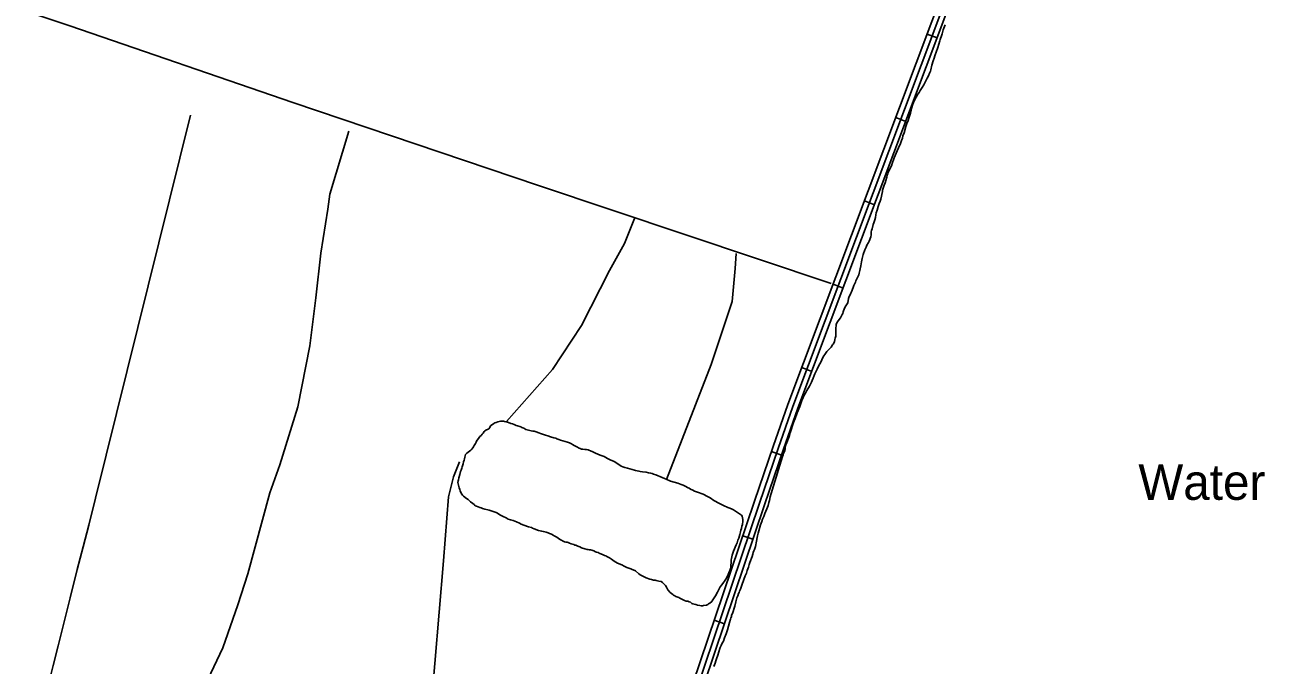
# Model space of a CAD drawing. Extents: x 3177185 to 3215018, y 812988 to 838321.
# Drawn here: x 3191874 to 3195360, y 828371 to 830168 of the extents above; entities that cross this region are included whole.
import ezdxf

# ---------------------------------------------------------------- set-up
doc = ezdxf.new("R2010")
doc.units = 0
for name, color, linetype in [('V-RIVR-IDEN', 7, 'Continuous'), ('V-ROAD-CNTR', 7, 'Continuous'), ('V-TOPO-SHOR', 7, 'Continuous')]:
    doc.layers.add(name, color=color, linetype=linetype)

msp = doc.modelspace()

# ---------------------------------------------------------------- linework, layer by layer
at = {"layer": 'V-ROAD-CNTR'}
for p, q in [((3194436, 830131.4), (3194407.9, 830141.9)), ((3194347.9, 829897.4), (3194319.9, 829908)), ((3194259.9, 829663.4), (3194231.8, 829674)), ((3194171.8, 829429.4), (3194143.7, 829440)), ((3194083.8, 829195.5), (3194055.7, 829206)), ((3193998.9, 828960.8), (3193970.5, 828970.5)), ((3193918.4, 828724.2), (3193890, 828733.8)), ((3193838.5, 828487.3), (3193810, 828496.9))]:
    msp.add_line(p, q, dxfattribs=at)
for points in [[(3195718.2, 830676.6), (3195274.2, 830649.9), (3194889.5, 830614.4), (3194691.9, 830585.5), (3194661.2, 830576.1), (3194620.2, 830551.7), (3194549, 830454.1), (3194520.5, 830401.6), (3194435.4, 830172.3), (3194030.8, 829097.3), (3193989.4, 828979.4), (3193936.9, 828826), (3193655, 827990.6), (3193436.5, 827403.7), (3193231, 826864.7), (3193164.5, 826701.3), (3193149.1, 826671.9), (3192991.1, 826299.7)], [(3195718.9, 830661.6), (3195275.3, 830635), (3194891.3, 830599.5), (3194695.2, 830570.8), (3194667.4, 830562.3), (3194630.5, 830540.4), (3194561.7, 830446.1), (3194534.2, 830395.4), (3194449.4, 830167), (3194044.9, 829092.1), (3194003.6, 828974.5), (3193951.1, 828821.2), (3193669.2, 827985.5), (3193450.5, 827398.5), (3193245, 826859.2), (3193178.1, 826695), (3193162.7, 826665.5), (3193032.9, 826359.8)], [(3194509.8, 830415.8), (3194421.3, 830177.5), (3194016.7, 829102.4), (3193975.3, 828984.3), (3193922.7, 828830.8), (3193640.9, 827995.6), (3193422.4, 827409), (3193217, 826870.2), (3193150.8, 826707.7), (3193135.5, 826678.3), (3192977.5, 826306.2), (3192932.7, 826221.9), (3192888.6, 826141.9), (3192857.2, 826099.8), (3192822.1, 826060.4), (3192768.4, 826005.4), (3192712.2, 825957.6), (3192677.2, 825934.2), (3192621.8, 825905.4)]]:
    msp.add_lwpolyline(points, dxfattribs=at)
at = {"layer": 'V-TOPO-SHOR'}
msp.add_line((3192072.2, 828839.8), (3192339, 829914.9), dxfattribs=at)
for points in [[(3190402.1, 830713), (3190848.1, 830553.1), (3191672.8, 830275.4), (3192001, 830166), (3192626.6, 829950), (3193316.6, 829717.1), (3194138.6, 829442.2)], [(3194245.1, 829561.1), (3194249.6, 829573.2), (3194250.5, 829579.2), (3194250.5, 829582.6), (3194251.1, 829587.1), (3194252, 829590.7), (3194253.2, 829596.1), (3194256.2, 829607.6), (3194258, 829612.2), (3194259.5, 829615.5), (3194261.3, 829620.6), (3194262.5, 829627.3), (3194264.3, 829635.4), (3194265.2, 829640.2), (3194267.6, 829648.4), (3194270.6, 829658.1), (3194270.9, 829661.1), (3194273.3, 829666.5), (3194276.3, 829673.2), (3194277.5, 829678.9), (3194282.2, 829700.6), (3194282.8, 829704), (3194285.5, 829712.4), (3194287.6, 829718.1), (3194289.7, 829724.5), (3194291.5, 829731.4), (3194294.5, 829740.5), (3194296, 829746.2), (3194297.2, 829749.9), (3194298.4, 829753.8), (3194301.1, 829760.7), (3194307.4, 829772.2), (3194310.7, 829781.9), (3194313.1, 829789.1), (3194314.9, 829795.2), (3194320.9, 829808.2), (3194324, 829814.2), (3194327.9, 829822.7), (3194333.3, 829835.6), (3194336.3, 829844.1), (3194338.4, 829850.1), (3194339.9, 829856.5), (3194343.2, 829865.2), (3194348.3, 829883.4), (3194351, 829891.5), (3194354.3, 829900), (3194357.3, 829909), (3194360.9, 829920.8), (3194361.8, 829923.8), (3194364.1, 829933.2), (3194368, 829945.3), (3194372.2, 829956.7), (3194382.2, 829973.4), (3194385.5, 829978.8), (3194388.2, 829983.9), (3194391.8, 829989.7), (3194393.9, 829992.7), (3194398.4, 830000.3), (3194402, 830007.5), (3194405, 830012.9), (3194407.7, 830018.4), (3194411.3, 830025), (3194414.9, 830032.9), (3194417.3, 830038.3), (3194418.5, 830041.6), (3194421.2, 830054.9), (3194424.5, 830067.3), (3194427.2, 830075.2), (3194429.6, 830080.9), (3194430.5, 830083.9), (3194432.9, 830091.2), (3194437.7, 830105.1), (3194444, 830123.5), (3194444.9, 830126.8), (3194447.9, 830137.4), (3194450, 830143.1), (3194452.1, 830150.4), (3194453.3, 830154.6), (3194458.1, 830168.5)], [(3192006.6, 827411.3), (3192062.7, 827740.9), (3192079.6, 827785.8), (3192099.2, 827836.3), (3192135.7, 827895.2), (3192172.1, 827951.3), (3192247.9, 828057.9), (3192304, 828147.6), (3192379.7, 828313.1), (3192430.2, 828419.7), (3192472.3, 828540.4), (3192500.3, 828627.3), (3192562, 828854.5), (3192590.1, 828933.1), (3192640.6, 829095.8), (3192674.3, 829266.9), (3192691.1, 829401.6), (3192705.1, 829527.8), (3192724.7, 829651.2), (3192730.4, 829693.3), (3192783.7, 829870)], [(3193226.9, 829055.1), (3193355.9, 829201), (3193437.3, 829324.4), (3193515.8, 829478.7), (3193557.9, 829554.4), (3193585.9, 829624.6)], [(3193972.8, 828862.5), (3194001.9, 828956.4), (3194004, 828961.3), (3194004.9, 828965.5), (3194007.9, 828972.4), (3194009.1, 828978.8), (3194009.7, 828983.9), (3194011.5, 828989), (3194014.2, 828996), (3194015.4, 829000.5), (3194018.4, 829008.1), (3194020.2, 829012.3), (3194021.4, 829015.9), (3194023.5, 829023.2), (3194026.5, 829031.9), (3194031, 829046.7), (3194032.8, 829051.6), (3194037.3, 829063.3), (3194043.3, 829079.3), (3194050.2, 829096.9), (3194051.4, 829099.9), (3194054.1, 829108.6), (3194055.9, 829114.1), (3194059.5, 829121.9), (3194061.9, 829126.8), (3194066.1, 829134.6), (3194068.2, 829138.2), (3194070.3, 829141.9), (3194073, 829146.7), (3194075.2, 829149.4), (3194077.3, 829154), (3194083, 829165.4), (3194084.8, 829169.7), (3194088.1, 829176.9), (3194090.8, 829184.2), (3194092.9, 829188.7), (3194097.1, 829198.1), (3194098.9, 829201.7), (3194100.4, 829205), (3194102.5, 829208.9), (3194105.2, 829214.1), (3194106.7, 829217.1), (3194110.9, 829224.9), (3194112.4, 829228), (3194114.5, 829232.8), (3194118.1, 829239.4), (3194120.5, 829243.1), (3194122.3, 829246.1), (3194125.9, 829251.5), (3194135.9, 829260.9), (3194138.3, 829263.9), (3194142.5, 829269.7), (3194144.3, 829272.1), (3194147.6, 829278.4), (3194148.8, 829285.4), (3194150, 829289), (3194151.2, 829294.7), (3194151.2, 829305), (3194151.2, 829309.2), (3194151.2, 829313.8), (3194151.2, 829318), (3194152.4, 829323.4), (3194152.9, 829327), (3194155.6, 829334), (3194164.4, 829345.8), (3194166.8, 829350), (3194169.5, 829355.4), (3194171, 829358.2), (3194172.5, 829362.4), (3194176.1, 829373), (3194179.7, 829379.3), (3194181.8, 829382), (3194183.6, 829384.7), (3194184.8, 829388.4), (3194187.2, 829400.1), (3194189.3, 829405.3), (3194192.3, 829411.9), (3194193.8, 829415.2), (3194195.6, 829418.6), (3194199.8, 829431), (3194202.2, 829436.4), (3194204.9, 829442.7), (3194206.4, 829446.4), (3194207.6, 829449.4), (3194209.7, 829453.9), (3194213.9, 829462.7), (3194215.7, 829466.6), (3194216.9, 829471.4), (3194219, 829478.7), (3194220.2, 829483.5), (3194221.4, 829491.7), (3194223.8, 829503.4), (3194225, 829507.7), (3194225.3, 829512.2), (3194226.2, 829515.8), (3194228.6, 829523.7), (3194233.1, 829537), (3194236.7, 829544.5), (3194238.8, 829549.9), (3194243, 829556.9), (3194245.1, 829561.1)], [(3193675.7, 828892.4), (3193801.9, 829215), (3193860.8, 829391.7), (3193869.3, 829484.3), (3193872.1, 829526.4)], [(3193126.4, 828974.7), (3193129.1, 828977.4), (3193131.8, 828980.5), (3193134.1, 828984.1), (3193136.3, 828987.6), (3193139.5, 828993.4), (3193141.3, 828996.5), (3193142.7, 828999.2), (3193144.5, 829002.3), (3193147.7, 829006.8), (3193152.2, 829013), (3193155.3, 829015.2), (3193158.5, 829019.3), (3193161.2, 829022.4), (3193163.9, 829026.4), (3193166.2, 829028.6), (3193170.2, 829031.3), (3193173.4, 829032.6), (3193177, 829034.3), (3193179.7, 829037.9), (3193182, 829042.4), (3193191.4, 829049), (3193194.1, 829050.8), (3193197.3, 829051.6), (3193202.7, 829053.8), (3193210.3, 829056), (3193214.3, 829056), (3193217.9, 829055.5), (3193221.5, 829055), (3193225.5, 829053.7), (3193229.5, 829053.2), (3193232.7, 829051.8), (3193238.5, 829049.5), (3193243.8, 829048.2), (3193248.3, 829046.3)], [(3193248.3, 829046.3), (3193254.1, 829044), (3193257.7, 829042.7)], [(3193257.7, 829042.7), (3193263.9, 829040.8), (3193266.6, 829039.5), (3193270.2, 829038.1), (3193275.1, 829036.3), (3193281.3, 829032.6), (3193292, 829029.9), (3193295.6, 829028.9), (3193300.5, 829028), (3193304.6, 829027.5), (3193310.4, 829026.1), (3193317.5, 829023.4), (3193322.4, 829021.1), (3193330.9, 829017.9), (3193336.3, 829016.5), (3193343, 829014.2), (3193350.6, 829012), (3193360, 829009.2), (3193364.9, 829007.8), (3193368.5, 829006.4), (3193373.4, 829004.6), (3193378.7, 829002.8), (3193398.4, 828996.4), (3193403.7, 828994.5), (3193409.1, 828991.8), (3193412.2, 828990), (3193416.7, 828987.3), (3193423.8, 828984.1), (3193430.9, 828980), (3193433.6, 828978.6), (3193437.2, 828977.2), (3193441.2, 828977.2), (3193446.6, 828976.7), (3193451.1, 828976.2), (3193456.4, 828975.3), (3193464.9, 828971.7), (3193467.6, 828970.3), (3193476.5, 828966.2), (3193489.5, 828960.7), (3193501.1, 828956.2), (3193506, 828953.9), (3193510.4, 828951.2), (3193518, 828947.5), (3193528.7, 828943), (3193542.1, 828934.3), (3193549.2, 828929.8), (3193553.3, 828927.5), (3193558.6, 828925.7), (3193566.7, 828923.4), (3193585.9, 828917.9), (3193589, 828917.4), (3193593.5, 828916.5), (3193598.8, 828915.5), (3193602, 828914.6), (3193608.2, 828913.7), (3193618.5, 828912.3), (3193625.2, 828910.9), (3193631.5, 828909.9), (3193635.5, 828908.5), (3193639.1, 828907.2), (3193646.2, 828904.9), (3193664.1, 828897.6), (3193670.8, 828894.4), (3193675.2, 828892.6), (3193678.4, 828891.2), (3193683.3, 828888.9), (3193687.7, 828887.1), (3193698, 828884.8), (3193707.4, 828882), (3193712.8, 828879.7), (3193717.2, 828877.9), (3193722.6, 828876.5), (3193728.8, 828872.9), (3193736.9, 828868.8), (3193739.5, 828867.4), (3193743.1, 828865.2), (3193750.2, 828862), (3193754.3, 828859.7), (3193762.7, 828856.5), (3193778.8, 828850.6), (3193790.9, 828844.2), (3193798.5, 828840.1), (3193809.1, 828833.3), (3193824.8, 828824.7), (3193830.6, 828821.5), (3193835.9, 828818.8), (3193848, 828813.8), (3193854.2, 828811.5), (3193860, 828808.3), (3193864, 828806.5), (3193869.4, 828803.3), (3193877.8, 828797.4), (3193886.3, 828791.5), (3193888.1, 828788.8), (3193889.8, 828784.8), (3193890.7, 828779.8), (3193890.7, 828774.9), (3193889.7, 828766), (3193887.9, 828760.6), (3193886.5, 828754.8), (3193885.1, 828749.4)], [(3193487.3, 828684.9), (3193483.8, 828686.7), (3193479.3, 828688.1), (3193476.6, 828689.4), (3193472.2, 828691.7), (3193466.4, 828693.5), (3193462.8, 828694.9), (3193459.6, 828694.5), (3193456.5, 828695.4), (3193452.9, 828695.9), (3193447.1, 828697.3), (3193437.3, 828700.5), (3193432.4, 828702.8), (3193427, 828704.6), (3193421.7, 828707.3), (3193418.5, 828707.8), (3193415.4, 828709.2), (3193412.3, 828710.1), (3193408.3, 828711.4), (3193403.4, 828713.7), (3193400.2, 828715.1), (3193396.7, 828716), (3193393.5, 828716), (3193390, 828717.4), (3193383.7, 828720.1), (3193381, 828721.5), (3193378.4, 828722.9), (3193372.1, 828727.4), (3193367.7, 828730.6), (3193361, 828734.2), (3193357.9, 828735.6), (3193353, 828738.3), (3193347.6, 828740.6), (3193344, 828742.4), (3193338.2, 828743.8), (3193330.2, 828745.6), (3193325.2, 828747), (3193321.7, 828747.9), (3193316.3, 828749.3), (3193304.3, 828753.9), (3193299.3, 828755.7), (3193296.7, 828757.1), (3193288.2, 828759.4), (3193275.7, 828763.5), (3193268.1, 828766.7), (3193263.2, 828769.4), (3193255.1, 828773.1), (3193245.3, 828776.7), (3193241.7, 828777.7), (3193238.2, 828778.6), (3193231.5, 828780.9), (3193226.1, 828784.1), (3193217.6, 828788.6), (3193211.4, 828791.3), (3193207.8, 828793.2), (3193201.1, 828797.2), (3193198, 828799.1), (3193194.9, 828800), (3193186.4, 828803.2), (3193183.3, 828804.1), (3193177.9, 828805.5), (3193173.9, 828807.3), (3193166.3, 828808.7), (3193159.6, 828810.5), (3193156, 828812.4), (3193152, 828813.3), (3193147.5, 828815.1), (3193142.2, 828816.9), (3193139, 828818.3), (3193135.9, 828821.5), (3193131.9, 828825.1), (3193126.1, 828829.6), (3193121.7, 828833.2), (3193119, 828835.9), (3193114.6, 828839.1), (3193106.1, 828845.4), (3193103, 828847.7), (3193101.2, 828850.4), (3193098.6, 828855.4), (3193096.8, 828859.8), (3193095.5, 828863.9), (3193093.8, 828868.8), (3193093.3, 828872), (3193090.3, 828883.6), (3193091.2, 828888.1), (3193091.7, 828891.2), (3193092.6, 828896.6), (3193095.8, 828906.4), (3193097.7, 828914.9), (3193099.1, 828918.5), (3193100.9, 828924.3), (3193101.8, 828927.9), (3193104.6, 828936.4), (3193106, 828941.3), (3193107.8, 828946.2), (3193109.2, 828949.8), (3193110.1, 828954.7), (3193111.9, 828962.3), (3193115.1, 828965.8), (3193118.7, 828969), (3193126.4, 828974.7)], [(3192536.8, 827060.6), (3192550.8, 827094.3), (3192570.5, 827113.9), (3192592.9, 827136.4), (3192629.4, 827156), (3192660.2, 827178.4), (3192677.1, 827200.9), (3192688.3, 827228.9), (3192727.5, 827296.3), (3192744.4, 827349.6), (3192764, 827408.5), (3192820.1, 827634.3), (3192867.8, 827783), (3192926.7, 828041), (3192935.1, 828097.1), (3192952, 828122.4), (3192974.4, 828147.6), (3192999.7, 828192.5), (3193013.7, 828231.8), (3193050.1, 828663.8), (3193064.2, 828843.3), (3193078.2, 828899.4), (3193095, 828941.5)], [(3193856.8, 828503.8), (3193858.1, 828506.9), (3193858.6, 828510), (3193862.3, 828518.5), (3193867.3, 828533.2), (3193867.8, 828536.8), (3193871, 828548.9), (3193871.5, 828552), (3193873.8, 828560.1), (3193876, 828565), (3193878.3, 828571.7), (3193879.7, 828574.8), (3193881.1, 828578.4), (3193882.5, 828582.4), (3193884.7, 828586.9), (3193888.8, 828598.5), (3193897.1, 828621.2), (3193900.3, 828628.8), (3193902.6, 828636.4), (3193906.7, 828646.3), (3193908.5, 828653.4), (3193910.4, 828658.8), (3193916.3, 828676.2), (3193918.2, 828682), (3193919.5, 828686.9), (3193921.4, 828691.4), (3193922.7, 828695.4), (3193925.5, 828704.3), (3193928.3, 828718.6), (3193930.6, 828728.9), (3193932, 828734.3), (3193933.4, 828741), (3193935.2, 828748.1), (3193940.3, 828764.7), (3193943.5, 828774.5), (3193945.8, 828780.3), (3193949, 828788.3), (3193952.6, 828796.4), (3193958.1, 828809.8), (3193961.3, 828819.1), (3193963.6, 828827.2), (3193965, 828833.5), (3193967.3, 828843.7), (3193969.2, 828850), (3193970.5, 828855.8), (3193972.8, 828862.5)], [(3191919.3, 828234.1), (3191929.2, 828274.7), (3191940.7, 828317.4), (3191954, 828369.9), (3191967.8, 828425.2), (3191984.9, 828492.6), (3192001.2, 828560), (3192021.5, 828639), (3192038.3, 828703.1), (3192053.7, 828764.2), (3192072.2, 828839.8)], [(3193885.1, 828749.4), (3193883.7, 828745.4), (3193881.9, 828737.4), (3193879.1, 828727.1), (3193876.4, 828721.7), (3193874.1, 828714.6), (3193871.8, 828708.8), (3193864, 828690.9), (3193860.8, 828679.7), (3193859.9, 828675.3), (3193858.9, 828669.9), (3193858, 828666.3), (3193858, 828660.1), (3193856.5, 828649.3), (3193856.5, 828646.2), (3193855.6, 828642.6), (3193853.8, 828636.4), (3193851.5, 828630.1), (3193849.2, 828625.6), (3193847.4, 828621.2), (3193844.2, 828614.9), (3193841, 828609.6), (3193838.7, 828606.5), (3193836.5, 828602.9), (3193831.5, 828596.2), (3193827, 828590.4), (3193823.3, 828583.7), (3193820.2, 828577.9), (3193818.8, 828575.3), (3193816.5, 828571.3), (3193815.2, 828568.6), (3193813.8, 828565.9), (3193809.7, 828560.1), (3193805.7, 828553.9), (3193802.9, 828549.9), (3193797.5, 828544.5), (3193794.4, 828542.8), (3193791.7, 828541.4), (3193788.1, 828539.2), (3193780.4, 828537.9), (3193777.3, 828537.1), (3193774.2, 828537.1), (3193770.1, 828538), (3193763, 828539.4), (3193758.5, 828541.3), (3193753.6, 828542.2), (3193750, 828542.7), (3193746.9, 828544), (3193743.4, 828547.6), (3193739.3, 828549), (3193736.2, 828550.4), (3193731.3, 828550.9), (3193726.4, 828552.2), (3193722.4, 828554.1), (3193713.4, 828558.6), (3193710.3, 828560.4), (3193702.7, 828563.2), (3193699.2, 828565.9), (3193696, 828567.7), (3193693.4, 828569.5), (3193690.2, 828572.2), (3193686.7, 828574.5), (3193680, 828582.2), (3193678.3, 828586.2), (3193676.1, 828589.8), (3193673.4, 828594.3), (3193670.7, 828597), (3193665, 828602.9), (3193660.9, 828605.6), (3193654.7, 828607), (3193647.1, 828608.8), (3193644, 828609.3), (3193639.9, 828609.8), (3193634.1, 828611.2), (3193629.6, 828612.1), (3193618.5, 828615.8), (3193611.3, 828619.4), (3193605.5, 828622.1), (3193602.4, 828624), (3193598, 828627.6), (3193588.6, 828635.3), (3193582.8, 828638.4), (3193579.7, 828639.8), (3193575.7, 828641.2), (3193569.9, 828643.5), (3193564.5, 828645.3), (3193560.9, 828646.7), (3193557.4, 828648.5), (3193550.2, 828652.1), (3193538.2, 828657.6), (3193534.2, 828659.9), (3193528.8, 828663), (3193525.7, 828665.3), (3193521.3, 828668.5), (3193516.4, 828672.1), (3193508.3, 828676.2), (3193505.7, 828678), (3193502.1, 828678.9), (3193496.7, 828681.7), (3193493.1, 828682.6), (3193487.3, 828684.9)], [(3193808.7, 828367.5), (3193812.3, 828376.5), (3193814.6, 828383.2), (3193816.9, 828389), (3193820.1, 828398.8), (3193826.1, 828417.6), (3193826.6, 828420.7), (3193829.3, 828426.5), (3193832, 828432.3), (3193836.1, 828438.5), (3193839.3, 828447.5), (3193843.4, 828459.1), (3193847.5, 828469.8), (3193852.6, 828490.4), (3193855.4, 828499.8), (3193856.8, 828503.8)]]:
    msp.add_lwpolyline(points, dxfattribs=at)

# ---------------------------------------------------------------- texts
at = {"layer": 'V-RIVR-IDEN'}
msp.add_text('Water', height=100, dxfattribs=at).set_placement((3195001, 828834.9))

doc.saveas('drawing.dxf')
